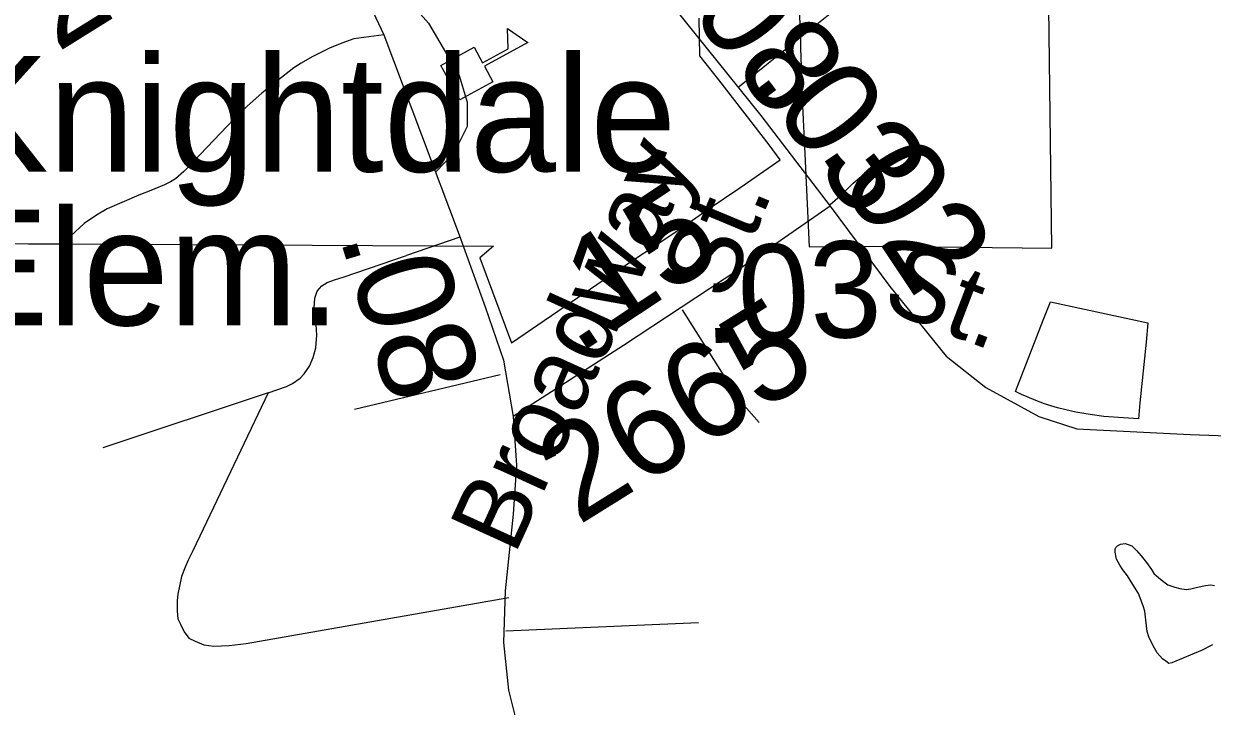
# Model space of a CAD drawing. Extents: x 2001466 to 31450019, y -30647475 to 847247.
# Drawn here: x 2153439 to 2156522, y 738837 to 740607 of the extents above; entities that cross this region are included whole.
import ezdxf

# ---------------------------------------------------------------- set-up
doc = ezdxf.new("R2010")
doc.units = 0
for name, color, linetype in [('Exist Boundary Political City Limit New', 7, 'Continuous'), ('Exist Cultural Educational Facility Elementary CELL', 7, 'Continuous'), ('Exist Cultural Educational Facility Elementary Label', 7, 'Continuous'), ('Exist Hydrographic Misc Water Feature', 7, 'Continuous'), ('Exist Road Non-System Type 51', 7, 'Continuous'), ('Exist Road Secondary Mileage Hundredths English Label', 7, 'Continuous'), ('Exist Road Secondary Type 51 Attributed', 7, 'Continuous'), ('Exist Road Secondary Type 51 Label', 7, 'Continuous'), ('Exist Road Secondary Type 51 Number Label', 7, 'Continuous'), ('Map Preparation Boundary City Limit Buffer Line', 7, 'Continuous')]:
    doc.layers.add(name, color=color, linetype=linetype)

msp = doc.modelspace()

# ---------------------------------------------------------------- linework, layer by layer
at = {"layer": 'Exist Boundary Political City Limit New'}
for points in [[(2155446.5, 740691.4), (2155452.5, 740595.3), (2155453.5, 740545.1), (2155459, 740393.9), (2155464.8, 740269.3), (2155475.8, 740028.2), (2155642.5, 740030.4), (2156106, 740024.6), (2156094.2, 740927.1)], [(2152943.5, 740037.1), (2153450.8, 740036.3), (2153560, 740036.2), (2154657.2, 740029.8), (2154622.2, 740000), (2154703.5, 739779.2), (2154960.5, 739954.6), (2155132.5, 740069.3), (2155214.2, 740125.8), (2155296.5, 740181.9), (2155401.2, 740254.1), (2155372.2, 740292.9), (2155241.8, 740461.6), (2155192.8, 740523.8), (2155190.8, 740621.7)], [(2156334.2, 739623.9), (2156330.2, 739582.6), (2156291.5, 739584.6), (2156241, 739588.4), (2156204.8, 739593.1), (2156189, 739595.7), (2156168, 739599.6), (2156141.8, 739605.6), (2156120.8, 739611.1), (2156094.5, 739618.9), (2156086.8, 739621.5), (2156064.2, 739629.8), (2156041.8, 739638.9), (2156027, 739645.6), (2156011.2, 739653.2), (2156083.5, 739838.2), (2156102.5, 739885.6), (2156355, 739831.6), (2156350.2, 739781.5), (2156334.2, 739623.9)]]:
    msp.add_lwpolyline(points, dxfattribs=at)
at = {"layer": 'Exist Cultural Educational Facility Elementary CELL'}
msp.add_lwpolyline([(2154521, 740499.1), (2154607, 740546.1), (2154629, 740505.7), (2154694.9, 740541.7), (2154693.6, 740594.6), (2154746.4, 740558.9), (2154633.6, 740497.3), (2154655.7, 740456.9), (2154569.8, 740409.9)], close=True, dxfattribs=at)
at = {"layer": 'Exist Hydrographic Misc Water Feature'}
msp.add_lwpolyline([(2156522.9, 738995.8), (2156519, 738994), (2156495.4, 738981.7), (2156417.3, 738949.3), (2156409.3, 738947.3), (2156401.3, 738953.3), (2156393.1, 738959.5), (2156379.2, 738975.4), (2156368.9, 738993.1), (2156357.2, 739016.8), (2156352.7, 739030.9), (2156350.9, 739045), (2156347, 739082.9), (2156342.5, 739096.9), (2156330.4, 739128.8), (2156316, 739152.8), (2156302.3, 739174.8), (2156290, 739190.5), (2156281.8, 739202.6), (2156273.8, 739218.5), (2156269.7, 739236.5), (2156269.7, 739244.6), (2156271.7, 739248.4), (2156275.8, 739252.6), (2156283.6, 739256.7), (2156295.9, 739258.5), (2156303.5, 739256.5), (2156313.6, 739252.6), (2156325.7, 739240.6), (2156337.8, 739227), (2156351.7, 739209.1), (2156364, 739191), (2156370.2, 739181.2), (2156388.2, 739165), (2156406.4, 739151.3), (2156424.5, 739145.3), (2156438.2, 739141.7), (2156454.2, 739139.7), (2156465.9, 739141.6), (2156484, 739145.7), (2156504.3, 739149.9), (2156518.2, 739151.9), (2156528, 739150)], dxfattribs=at)
at = {"layer": 'Exist Road Non-System Type 51'}
for p, q in [((2155291.2, 740442.2), (2155444.1, 740564.7)), ((2154570.2, 740053.7), (2154431.1, 740006)), ((2154674.1, 739696.1), (2154296.9, 739606.3)), ((2154072.4, 739649.9), (2153644, 739507.3)), ((2154689.1, 739032.3), (2155189, 739053.6))]:
    msp.add_line(p, q, dxfattribs=at)
for points in [[(2155444.1, 740564.7), (2155639, 740721), (2155667.8, 740718.8), (2155694.4, 740709.9), (2155862.8, 740672.2)], [(2154317.7, 740695.7), (2154346.1, 740702.3), (2154412.1, 740695.3), (2154488.5, 740608.4), (2154568.4, 740472.9), (2154589.2, 740403.4), (2154589.2, 740340.8), (2154554.5, 740271.3), (2154506.9, 740222)], [(2154372.5, 740578.7), (2154294.6, 740568.2), (2154263.6, 740556.6), (2154231.6, 740543.7), (2154211.1, 740533.3), (2154187.1, 740521), (2154158, 740505.2), (2154139.5, 740492.6), (2154095.4, 740458.3), (2154056.6, 740426.9), (2154018.5, 740393.3), (2153984.8, 740360.8), (2153895.9, 740267.8), (2153876.1, 740247.6), (2153854.2, 740223.5), (2153832.5, 740205.1), (2153819.5, 740196.8), (2153803.3, 740188.9), (2153778.3, 740179), (2153772.9, 740176.5), (2153737, 740162.3), (2153699.1, 740145.9), (2153655.3, 740127.4), (2153627.6, 740110.9), (2153595.7, 740088.8), (2153560, 740056.3)], [(2155530.4, 740137.9), (2155563.6, 740166.7), (2155590.2, 740193.3), (2155621.3, 740219.9), (2155652.3, 740246.5), (2155678.9, 740251), (2155689.3, 740248.4)], [(2154072.4, 739649.9), (2154120.4, 739666.3), (2154135.9, 739673.8), (2154155.4, 739687.6), (2154166, 739698.7), (2154179.8, 739718.9), (2154189.5, 739741.1), (2154196.2, 739766.1), (2154197.4, 739777.7), (2154198.9, 739799.1), (2154196.5, 739841.1), (2154192.2, 739868.6), (2154192.2, 739869), (2154193.9, 739895.1), (2154199.6, 739913.2), (2154211.5, 739927.2), (2154225.5, 739935.5), (2154247.4, 739943.6), (2154267.4, 739949.8), (2154431.1, 740006)], [(2155147, 739865.2), (2155273.4, 739663.4), (2155293.3, 739632.4), (2155346.5, 739572.5)], [(2154072.4, 739649.9), (2153876.8, 739239.7), (2153865.2, 739215.6), (2153857.2, 739197.5), (2153847.5, 739173.3), (2153837.9, 739127.3), (2153836.2, 739111.2), (2153836.4, 739083.2), (2153838.6, 739063.3), (2153844.9, 739049.4), (2153855.1, 739029.4), (2153867.2, 739013.5), (2153883.2, 739005.8), (2153905.4, 738996), (2153931.6, 738992.2), (2153971.4, 738994.6), (2154015.5, 738999.1), (2154697.2, 739119.1)]]:
    msp.add_lwpolyline(points, dxfattribs=at)
at = {"layer": 'Exist Road Secondary Type 51 Attributed'}
for points in [[(2154110.3, 742063), (2154154.9, 741996.5), (2154448.9, 741537.9), (2154666.6, 741213.2), (2154929.2, 740892.8), (2155350.9, 740369.3), (2155530.9, 740133.7)], [(2153638.8, 741844.3), (2153644.8, 741834.2), (2153723.8, 741728.4), (2153851.4, 741558.8), (2153943.5, 741420.6), (2154070.1, 741194.4), (2154214.5, 740915.9), (2154372.5, 740578.7), (2154568.2, 740059.3), (2154635.2, 739872.9), (2154683.3, 739734.7), (2154707.9, 739588.1)], [(2155530.9, 740133.7), (2155685.2, 739925.3), (2155831.7, 739745.2), (2155934.3, 739663.5), (2156072.4, 739588.1), (2156170.7, 739556.7), (2156464.8, 739542), (2156975.4, 739523.2), (2157322.8, 739508.5), (2157465.1, 739519), (2157601.2, 739548.3), (2157728.8, 739588.1), (2157845, 739650.9), (2158173.5, 739881.3), (2158437.2, 740067.7), (2158571.2, 740128.4), (2158688.3, 740168.2), (2158795.1, 740187.1), (2158879.8, 740185), (2159212.6, 740197.5), (2159666.7, 740199.6), (2159826.8, 740189.1)], [(2155530.9, 740133.7), (2155293.9, 739969.3), (2154994.6, 739772.4), (2154707.9, 739588.1)], [(2154707.9, 739588.1), (2154716.8, 739462.4), (2154708.4, 739334.7), (2154687.5, 739135.7), (2154683.3, 739001.7), (2154695.9, 738878.1), (2154757.6, 738633.1), (2154893.6, 738201.7), (2154961.6, 738038.4), (2155051.6, 737900.1), (2155248.4, 737621.6), (2155390.7, 737441.5), (2155510.5, 737303.3)]]:
    msp.add_lwpolyline(points, dxfattribs=at)
at = {"layer": 'Map Preparation Boundary City Limit Buffer Line'}
for points in [[(2155446.5, 740691.4), (2155452.5, 740595.3), (2155453.5, 740545.1), (2155459, 740393.9), (2155464.8, 740269.3), (2155475.8, 740028.2), (2155642.5, 740030.4), (2156106, 740024.6), (2156094.2, 740927.1)], [(2152943.5, 740037.1), (2153450.8, 740036.3), (2153560, 740036.2), (2154657.2, 740029.8), (2154622.2, 740000), (2154703.5, 739779.2), (2154960.5, 739954.6), (2155132.5, 740069.3), (2155214.2, 740125.8), (2155296.5, 740181.9), (2155401.2, 740254.1), (2155372.2, 740292.9), (2155241.8, 740461.6), (2155192.8, 740523.8), (2155190.8, 740621.7)], [(2156334.2, 739623.9), (2156330.2, 739582.6), (2156291.5, 739584.6), (2156241, 739588.4), (2156204.8, 739593.1), (2156189, 739595.7), (2156168, 739599.6), (2156141.8, 739605.6), (2156120.8, 739611.1), (2156094.5, 739618.9), (2156086.8, 739621.5), (2156064.2, 739629.8), (2156041.8, 739638.9), (2156027, 739645.6), (2156011.2, 739653.2), (2156083.5, 739838.2), (2156102.5, 739885.6), (2156355, 739831.6), (2156350.2, 739781.5), (2156334.2, 739623.9)]]:
    msp.add_lwpolyline(points, dxfattribs=at)

# ---------------------------------------------------------------- texts
at = {"layer": 'Exist Cultural Educational Facility Elementary Label'}
for s, p in [('Knightdale', (2153235.4, 740223.2)), ('Elem.', (2153235.4, 739824.8))]:
    msp.add_text(s, height=300, dxfattribs=at).set_placement(p)
at = {"layer": 'Exist Road Secondary Mileage Hundredths English Label'}
for s, rotation, p in [('.08', 308.176, (2155103.9, 740715.8)), ('.03', 307.3181, (2155321.9, 740461.4)), ('.02', 303.646, (2155499.8, 740275.5)), ('.15', 33.5817, (2154875.2, 739747)), ('.08', 286.8953, (2154256.8, 740055.3)), ('.03', 2.4477, (2155203.3, 739777.4))]:
    msp.add_text(s, height=250, rotation=rotation, dxfattribs=at).set_placement(p)
at = {"layer": 'Exist Road Secondary Type 51 Label'}
for s, rotation, p in [('Broadway', 65.4997, (2154711.8, 739225.9)), ('St.', 67.3442, (2155262.1, 739883)), ('St.', 339.0392, (2155659.4, 739869.4))]:
    msp.add_text(s, height=190, rotation=rotation, dxfattribs=at).set_placement(p)
at = {"layer": 'Exist Road Secondary Type 51 Number Label'}
for s, p in [('2233', (2153525.3, 740531.5)), ('2665', (2154876.9, 739304.5))]:
    msp.add_text(s, height=250, rotation=31.918, dxfattribs=at).set_placement(p)

doc.saveas('drawing.dxf')
